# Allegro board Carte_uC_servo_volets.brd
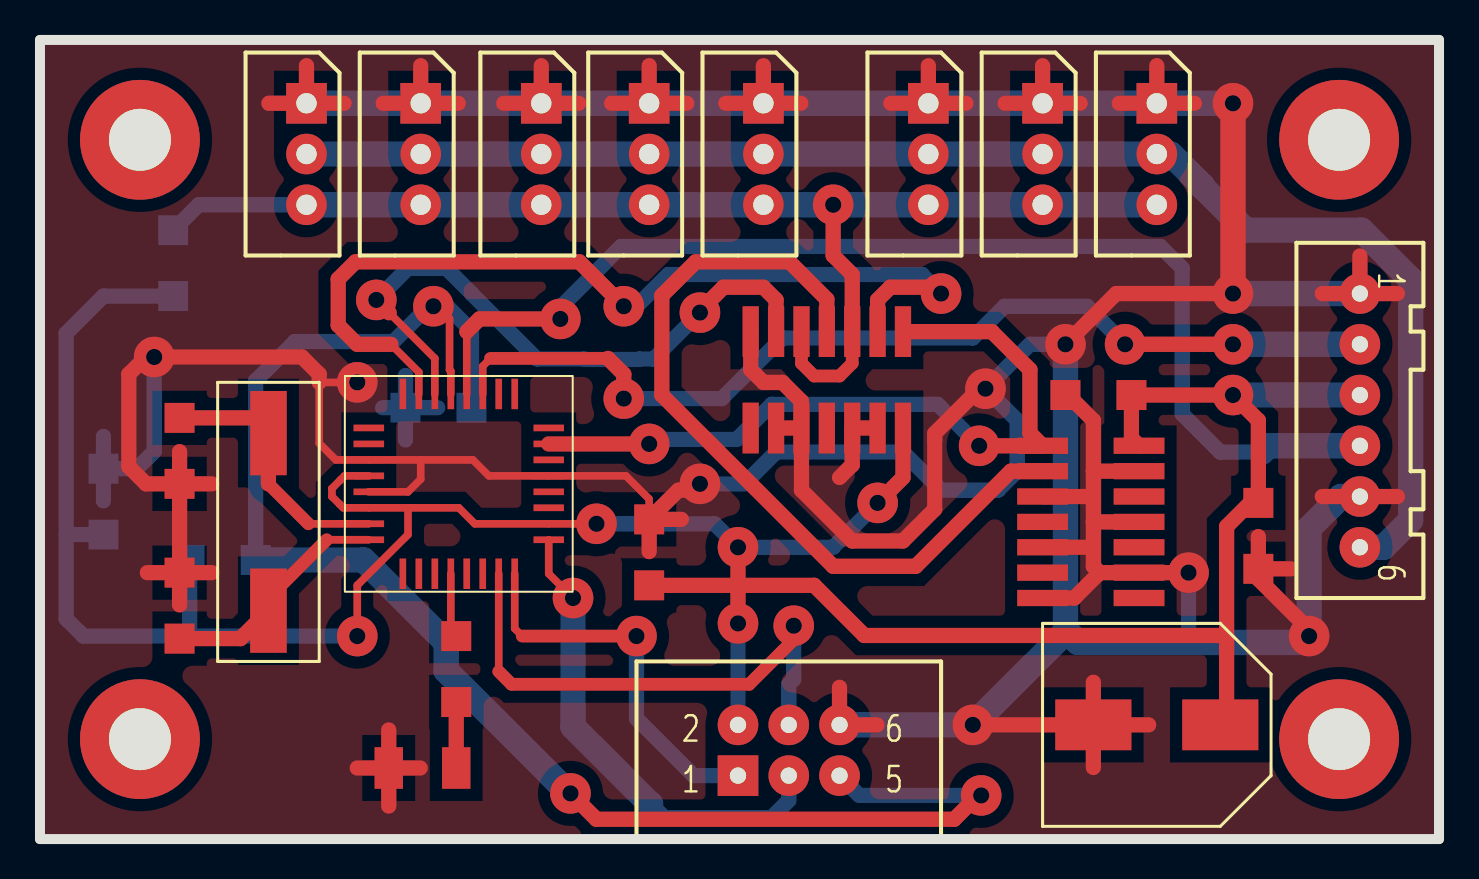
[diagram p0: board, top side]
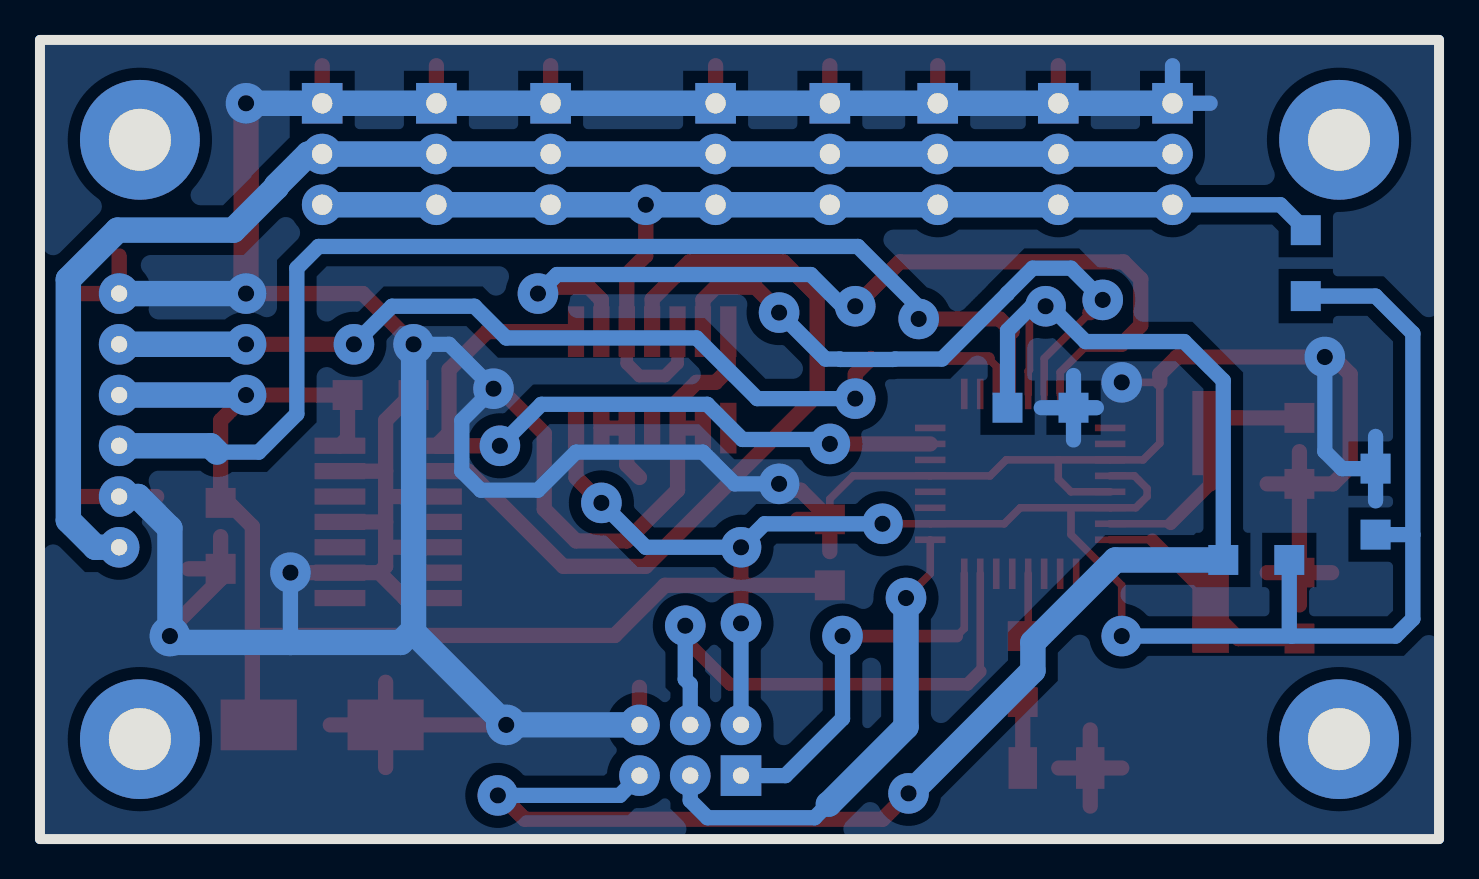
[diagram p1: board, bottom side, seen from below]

Outline 70 x 40 mm; copper layers: TOP, BOTTOM. Coordinates in mm from the lower left corner of the outline.

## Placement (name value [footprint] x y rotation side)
C2  22pF  [C_CMS]  6.99 13.34 270 top
C3  22pF  [C_CMS]  6.99 17.78 90 top
C5  10uF  [CAPA_CMS_F]  60.33 5.71 180 top
C6  100nF  [C_CMS]  60.96 16.83 270 top
C7  100nF  [C_CMS]  3.17 15.24 90 bottom
C8  100nF  [C_CMS]  54.61 22.23 180 top
C9  100nF  [C_CMS]  30.48 12.7 90 top
C10  100nF  [C_CMS]  21.59 21.59 180 bottom
D1  LED  [LED_CMS2]  20.83 3.56 0 top
J3  CON6  [EMBASE_XA_6P_D]  62.87 29.84 270 top
J5  CON3  [CON_AFFICHEUR]  36.2 36.83 270 top
J6  CON3  [CON_AFFICHEUR]  55.88 36.83 270 top
J7  CON3  [CON_AFFICHEUR]  50.16 36.83 270 top
J8  CON3  [CON_AFFICHEUR]  44.45 36.83 270 top
J9  CON3  [CON_AFFICHEUR]  30.48 36.83 270 top
J10  CON3  [CON_AFFICHEUR]  25.08 36.83 270 top
J11  CON3  [CON_AFFICHEUR]  19.05 36.83 270 top
J12  CON3  [CON_AFFICHEUR]  13.34 36.83 270 top
J13  HE10_6  [HE10_6D]  34.92 3.17 0 top
NOREF  -  [unnamed]  0 0 0 top
R24  10K  [R_CMS]  6.67 30.48 270 bottom
R25  470  [R_CMS]  20.83 10.16 270 top
R26  10K  [R_CMS]  10.79 13.97 180 bottom
U1  ATmega168  [TQFP32]  20.95 17.78 0 top
U6  74HC126  [DIL_14_CMS]  43.18 25.4 180 top
U7  74HC04  [DIL_14_CMS]  50.16 19.68 270 top
Y1  20MHz  [QUARTZ_CMS]  11.43 21.59 270 top

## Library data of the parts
C2 C3 C6-C10 = CAPACITOR NON-POL
C5 = CAPACITOR
D1 = LED
J3 = CON6
J5-J12 = CON3
J13 = HE10_6
R24-R26 = R
U1 = PIC16F84_0
U6 = 74HC126
U7 = 74HC04
Y1 = OSC6/SM_0

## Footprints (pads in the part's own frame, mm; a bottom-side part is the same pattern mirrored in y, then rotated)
C_CMS
  rect 1.499x1.499 smd: 1(0,0) 2(3.302,0)
CAPA_CMS_F
  rect 3.81x2.54 smd: 1(1.27,0) 2(7.62,0)
CON_AFFICHEUR
  rect 2.032x2.032 hole 1.016: 1(0,0)
  round 2.032 hole 1.016: 2(2.54,0) 3(5.08,0)
DIL_14_CMS
  rect 0.813x2.54 smd: 1(0,0) 2(1.27,0) 3(2.54,0) 4(3.81,0) 5(5.08,0) 6(6.35,0) 7(7.62,0) 8(7.62,4.826) 9(6.35,4.826) 10(5.08,4.826) 11(3.81,4.826) 12(2.54,4.826) 13(1.27,4.826) 14(0,4.826)
EMBASE_XA_6P_D
  round 2.032 hole 0.813: 1(2.54,3.175) 2(5.08,3.175) 3(7.62,3.175) 4(10.16,3.175) 5(12.7,3.175) 6(15.24,3.175)
HE10_6D
  rect 2.032x2.032 hole 0.813: 1(0,0)
  round 2.032 hole 0.813: 2(0,2.54) 3(2.54,0) 4(2.54,2.54) 5(5.08,0) 6(5.08,2.54)
LED_CMS2
  rect 1.422x2.083 smd: 1(0,0) 2(-3.378,0)
QUARTZ_CMS
  rect 4.216x1.829 smd: 1(1.27,0) 2(10.16,0)
R_CMS
  rect 1.499x1.499 smd: 1(0,0) 2(3.302,0)
TQFP32
  rect 1.524x0.33 smd: 1(-4.501,2.799) 2(-4.501,1.999) 3(-4.501,1.199) 4(-4.501,0.399) 5(-4.501,-0.399) 6(-4.501,-1.199) 7(-4.501,-1.999) 8(-4.501,-2.799) 17(4.501,-2.799) 18(4.501,-1.999) 19(4.501,-1.199) 20(4.501,-0.399) 21(4.501,0.399) 22(4.501,1.199) 23(4.501,1.999) 24(4.501,2.799)
  rect 0.33x1.524 smd: 9(-2.799,-4.501) 10(-1.999,-4.501) 11(-1.199,-4.501) 12(-0.399,-4.501) 13(0.399,-4.501) 14(1.199,-4.501) 15(1.999,-4.501) 16(2.799,-4.501) 25(2.799,4.501) 26(1.999,4.501) 27(1.199,4.501) 28(0.399,4.501) 29(-0.399,4.501) 30(-1.199,4.501) 31(-1.999,4.501) 32(-2.799,4.501)
unnamed
  round 5.994 hole 3.099: (5.001,35.001) (5.001,5.001) (65.001,35.001) (65.001,5.001)

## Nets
GND: C2.1 C3.1 C5.2 C6.2 C7.2 C8.2 C9.2 C10.2 D1.2(1) J3.1 J3.5 J5.1 J6.1 J7.1 J8.1 J9.1 J10.1 J11.1 J12.1 J13.6 U1.3(GND#3) U1.5(GND#5) U1.21(GND#21) U6.7(GND) U6.9(1A) U6.10(1OE) U6.12(1A) U6.13(1OE) U7.3(A) U7.5(A) U7.7(GND) U7.9(A) U7.11(A) U7.13(A)
VCC: C5.1 C6.1 C7.1 C8.1 C9.1 J3.3 J13.2 R24.2 R26.2 U1.4(VCC#4) U1.6(VCC#6) U1.18(AVCC) U6.14(VCC) U7.14(VCC)
VCC MOTORS: J3.6 J5.2 J6.2 J7.2 J8.2 J9.2 J10.2 J11.2 J12.2
AREF: U1.20(AREF)
DIRECTION: U1.23(PC0 (ADC0)) U6.1(1OE) U7.1(A)
MISO: J13.1 U1.16(PB4 (MISO))
MOSI: J13.4 U1.15(PB3 (MOSI))
RESET: C10.1 J13.5 R26.1 U1.29(PC6 (R\E\S\E\T\))
RX: U1.30(PD0 (RXD)) U6.6(1Y)
SCK: J13.3 U1.17(PB5 (SCK))
SCL: J3.4 U1.28(PC5 (ADC5/SCL))
SDA: J3.2 U1.27(PC4 (ADC4/SDA))
TX: U1.31(PD1 (TXD)) U6.2(1A)
N1659649: C3.2 U1.7(PB6 (TOSC1)) Y1.1
N1659657: C2.2 U1.8(PB7 (TOSC2)) Y1.2
N1735763: J5.3 J6.3 J7.3 J8.3 J9.3 J10.3 J11.3 J12.3 R24.1 U6.3(1Y) U6.5(1A)
N1752051: U6.4(1OE) U7.2(Y)
N1850060: R25.1 U1.12(PB0 (CLK0))
N1851847: D1.1(2) R25.2

Pads without a net: U1 1 2 9 10 11 13 14 19 22 24 25 26 32; U6 8 11; U7 4 6 8 10 12

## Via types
v1: diameter 2.032, hole 0.813, TOP to BOTTOM, 33 vias

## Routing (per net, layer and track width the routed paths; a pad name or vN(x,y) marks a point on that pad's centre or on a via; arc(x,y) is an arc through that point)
GND: length 380.6
  TOP w0.381: 19.05,18.98 21.66,18.98 22.46,18.18 U1.21 29.32,18.18 30.48,17.02 C9.2 ; 19.05,18.98 U1.3 14.8,18.98 13.97,19.81 13.97,22.86 v1(15.88,22.86) ; 19.05,18.98 19.05,18.02 18.41,17.38 U1.5
  TOP w0.762: 52.7,15.88 54.99,15.88 ; 52.7,15.88 52.7,17.14 ; 52.7,15.88 52.7,14.61 ; 52.7,14.61 U7.5 ; 52.7,14.61 52.7,13.65 53.02,13.34 ; 53.02,13.34 v1(57.47,13.34) ; 53.02,13.34 51.75,12.06 U7.7 ; J9.1 30.48,38.71 ; J9.1 28.6,36.83 ; J9.1 32.36,36.83 ; 30.48,14.39 C9.2 ; C9.2 32.09,16 ; C9.2 31.94,17.46 32.7,17.46 v1(33.02,17.78) ; v1(51.31,24.77) 53.85,27.3 v1(59.69,27.3) ; 41.88,5.71 J13.6 40.01,7.59 ; v1(63.5,10.16) 63.5,10.48 60.96,13.02 C6.2 ; J8.1 46.33,36.83 ; J8.1 42.57,36.83 ; J8.1 44.45,38.71 ; C2.1 8.6,13.34 ; C2.1 6.99,11.72 ; C2.1 C3.1 ; C2.1 5.37,13.34 ; 64.16,27.3 J3.1 ; J3.1 67.92,27.3 ; J3.1 66.04,29.18 ; 54,36.83 J6.1 ; J6.1 57.76,36.83 ; J6.1 55.88,38.71 ; 23.2,36.83 J10.1 ; J10.1 25.08,38.71 ; J10.1 26.96,36.83 ; 40.01,18.1 40.64,18.73 U6.12 U6.13 ; 13.97,22.86 13.97,23.27 13.11,24.13 v1(5.71,24.13) 5.31,24.13 4.45,23.27 4.45,18.64 5.31,17.78 C3.1 ; 34.32,36.83 J5.1 ; J5.1 38.07,36.83 ; J5.1 36.2,38.71 ; 64.16,17.14 J3.5 67.92,17.14 ; J7.1 52.04,36.83 ; J7.1 48.29,36.83 ; J7.1 50.16,38.71 ; C3.1 8.6,17.78 ; C3.1 6.99,19.39 ; 52.7,18.41 U7.13 ; 52.7,18.41 52.7,17.14 ; 52.7,18.41 52.7,20.95 51.44,22.23 C8.2 ; C6.2 62.57,13.53 ; C6.2 60.96,15.14 ; 52.7,5.71 55.47,5.71 ; 52.7,5.71 52.7,7.85 ; 52.7,5.71 v1(46.67,5.71) ; 52.7,5.71 52.7,3.58 ; 52.7,17.14 U7.3 ; 17.45,1.65 D1.2 ; D1.2 19.02,3.56 ; D1.2 17.45,5.46 ; D1.2 15.88,3.56 ; U6.10 38.1,21.91 37.15,22.86 36.2,22.86 35.56,23.5 U6.7 ; U6.10 38.1,17.46 40.64,14.92 43.18,14.92 44.77,16.51 44.77,20.31 47,22.54 v1(47.31,22.54) ; U6.10 U6.9 ; 17.17,36.83 J11.1 ; J11.1 20.93,36.83 ; J11.1 19.05,38.71 ; J12.1 15.21,36.83 ; J12.1 13.34,38.71 ; J12.1 11.46,36.83
  TOP w1.27: v1(59.69,27.3) v1(59.69,36.83)
  BOTTOM w0.762: v1(5.71,24.13) 5.71,19.4 4.85,18.54 C7.2 ; 11.46,36.83 J12.1 13.34,38.71 ; 57.47,9.84 v1(57.47,13.34) ; 18.29,19.98 C10.2 ; C10.2 19.9,21.59 ; C10.2 17.14,21.59 ; C10.2 18.29,23.2 ; 3.17,16.93 C7.2 ; C7.2 3.17,20.15 ; 16.17,22.57 v1(15.88,22.86) ; v1(33.02,17.78) 35.24,17.78 36.83,19.37 43.18,19.37 45.09,17.46 47.94,17.46 48.9,18.41 48.9,20.95 v1(47.31,22.54) 49.53,24.77 v1(51.31,24.77)
  BOTTOM w1.27: 51.31,10.48 51.31,10.35 v1(46.67,5.71) J13.6 ; 51.31,10.48 51.94,9.84 63.18,9.84 v1(63.5,10.16) 63.5,15.56 65.09,17.14 J3.5 ; 51.31,10.48 v1(51.31,24.77) ; J12.1 J11.1 J10.1 J9.1 J5.1 J8.1 J7.1 J6.1 v1(59.69,36.83) ; v1(59.69,27.3) J3.1
VCC: length 156.1
  TOP w0.381: 18.41,16.58 18.41,15.24 15.88,12.7 v1(15.88,10.16) ; 18.41,16.58 U1.6 15.17,16.58 15,16.76 14.61,17.14 14.61,17.54 15.03,17.98 15.24,18.18 U1.4 ; 18.41,16.58 20.95,16.58 21.76,15.78 U1.18 v1(27.85,15.78)
  TOP w0.762: U6.14 43.18,18.1 v1(41.91,16.83) ; v1(34.92,14.61) 34.92,12.7 ; 34.92,12.7 38.73,12.7 41.24,10.19 59.37,10.19 ; 34.92,12.7 C9.1 ; 34.92,12.7 v1(34.92,10.79) ; 59.37,10.19 59.37,6.03 C5.1 ; 59.37,10.19 59.37,15.65 60.55,16.83 C6.1 60.96,20.95 v1(59.69,22.23) C8.1 ; 54.93,22.54 C8.1 ; C8.1 54.61,20.07 U7.14
  BOTTOM w0.762: R26.2 7.49,10.28 7.38,10.16 ; 1.31,15.24 1.31,25.31 3.17,27.18 R24.2 ; 1.31,15.24 C7.1 ; 1.31,15.24 1.31,11.02 2.17,10.16 7.38,10.16 ; 7.38,10.16 v1(15.88,10.16) ; v1(41.91,16.83) 39.69,14.61 v1(34.92,14.61) 33.75,15.78 v1(27.85,15.78) ; v1(34.92,10.79) J13.2
  BOTTOM w1.27: v1(59.69,22.23) J3.3
VCC MOTORS: length 73
  BOTTOM w1.27: J3.6 67.23,14.61 68.58,15.96 68.58,28.02 66.12,30.48 60.33,30.48 58.17,32.64 58.17,32.7 56.57,34.29 J6.2 J7.2 J8.2 J5.2 J9.2 J10.2 J11.2 J12.2
DIRECTION: length 37.6
  TOP w0.762: U6.1 47.62,25.4 49.53,23.5 49.53,20.32 U7.1 v1(46.99,19.68) ; v1(30.48,19.78) U1.23
  BOTTOM w0.762: v1(46.99,19.68) 44.91,21.76 36.61,21.76 34.85,20 31.34,20 31.11,19.78 v1(30.48,19.78)
MISO: length 19.4
  TOP w0.381: 24.13,10.16 23.75,10.54 U1.16
  TOP w0.635: v1(29.84,10.16) 24.13,10.16
  BOTTOM w0.762: v1(29.84,10.16) 29.84,6.03 32.7,3.17 J13.1
MOSI: length 26.6
  TOP w0.381: 22.95,8.39 U1.15
  TOP w0.635: 22.95,8.39 23.59,7.75 35.48,7.75 37.71,9.98 v1(37.71,10.68)
  BOTTOM w0.762: v1(37.71,10.68) 37.71,8 37.47,7.75 J13.4
RESET: length 81.4
  TOP w0.381: U1.29 20.56,23.42 20.49,23.48 20.49,26.05 19.87,26.67 v1(19.68,26.67)
  TOP w0.762: v1(26.54,2.29) 27.84,0.99 45.75,0.99 46.94,2.18 v1(47.09,2.18)
  BOTTOM w0.762: C10.1 21.59,25.45 20.37,26.67 v1(19.68,26.67) 19.46,26.67 17.69,24.9 12.75,24.9 10.79,22.95 R26.1 ; v1(47.09,2.18) 40.99,2.18 J13.5 40.01,2.84 ; v1(26.54,2.29) 26.47,2.29
  BOTTOM w1.27: 26.47,2.29 20.32,8.43 20.32,9.84 16.19,13.97 R26.1
RX: length 31.9
  TOP w0.381: U1.30 19.76,24.06 17.47,26.34
  TOP w0.762: v1(16.83,26.99) 17.47,26.34 ; U6.6 36.83,26.99 36.2,27.62 34.2,27.62 33.34,26.76 33.34,26.67 v1(33.02,26.35)
  BOTTOM w0.762: v1(16.83,26.99) 18.41,28.57 20.33,28.57 21.6,27.3 21.6,27.29 24.87,24.03 27.21,24.03 27.33,24.01 29.95,24.01 29.97,24.03 30.7,24.03 v1(33.02,26.35)
SCK: length 24.2
  TOP w0.381: U1.17 25.46,13.28 v1(26.67,12.06)
  BOTTOM w0.762: J13.3 37.47,1.93 36.6,1.07 31.24,1.07 30.56,1.75
  BOTTOM w1.27: 30.56,1.75 30.53,1.75 26.67,5.62 v1(26.67,12.06)
SCL: length 58.6
  TOP w0.381: U1.28 21.35,25.4
  TOP w0.762: v1(26.04,26.04) 21.99,26.04 21.35,25.4
  BOTTOM w0.762: v1(26.04,26.04) 26.04,26.62 29.08,29.66 56.06,29.66 57.15,28.57 57.15,21.27 59.05,19.37 61.15,19.37
  BOTTOM w1.27: J3.4 61.46,19.68 61.15,19.37
SDA: length 49.7
  TOP w0.381: 22.54,24.06 22.15,23.67 U1.27
  TOP w0.635: 28.42,24.06 22.54,24.06
  TOP w0.762: 28.42,24.06 29.21,23.27 v1(29.21,22.05) ; v1(54.29,24.77) v1(59.69,24.77)
  BOTTOM w0.762: v1(54.29,24.77) 52.39,26.67 48.26,26.67 46.67,25.08 37.15,25.08 34.11,22.05 v1(29.21,22.05)
  BOTTOM w1.27: v1(59.69,24.77) J3.2
TX: length 46.1
  TOP w0.381: U1.31 18.96,23.37 17.56,24.77
  TOP w0.762: 17.56,24.77 15.88,24.77 14.92,25.72 14.92,28.03 15.78,28.89 26.99,28.89 v1(29.21,26.67) ; v1(45.09,27.3) 44.77,27.62 42.55,27.62 41.91,26.99 U6.2
  BOTTOM w0.762: v1(45.09,27.3) 44.13,28.26 31.43,28.26 29.84,26.67 v1(29.21,26.67)
N1659649: length 13.2
  TOP w0.381: U1.7 13.43,15.78
  TOP w0.635: 13.43,15.78 11.43,17.78
  TOP w0.762: C3.2 10.67,21.08 Y1.1 11.43,17.78
N1659657: length 11.9
  TOP w0.381: Y1.2 11.43,12.06 ; 14.35,14.98 U1.8
  TOP w0.635: 11.43,12.06 14.35,14.98
  TOP w0.762: 6.99,10.03 10.03,10.03 Y1.2
N1735763: length 62.7
  TOP w0.635: U6.3 40.64,23.81 40.01,23.18 38.73,23.18 38.1,23.81 U6.5
  TOP w0.762: U6.3 40.64,28.26 39.69,29.21 v1(39.69,31.75)
  BOTTOM w0.762: J12.3 7.94,31.75 R24.1
  BOTTOM w1.27: J12.3 J11.3 J10.3 J9.3 J5.3 v1(39.69,31.75) J8.3 J7.3 J6.3
N1752051: length 40.9
  TOP w0.762: U6.4 39.37,27.02 37.5,28.89 32.8,28.89 31.11,27.2 31.11,22.23 39.69,13.65 43.81,13.65 48.58,18.41 U7.2
N1850060: length 3.2
  TOP w0.381: U1.12 20.56,10.43
  TOP w0.508: 20.56,10.43 R25.1
N1851847: length 3.3
  TOP w0.762: R25.2 D1.1

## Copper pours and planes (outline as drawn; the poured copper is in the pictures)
GND on TOP, BOTTOM: 0,40.01 0,0 69.85,0 69.85,40.01
